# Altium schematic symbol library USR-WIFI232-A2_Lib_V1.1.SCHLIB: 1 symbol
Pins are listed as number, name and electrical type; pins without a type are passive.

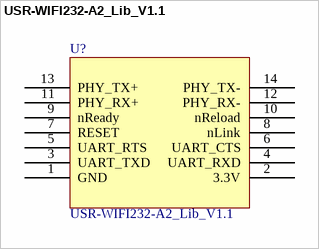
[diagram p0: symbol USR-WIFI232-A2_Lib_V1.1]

## USR-WIFI232-A2_Lib_V1.1
designator U?
footprint HA
pins: 1 GND, 2 3.3V, 3 UART_TXD, 4 UART_RXD, 5 UART_RTS, 6 UART_CTS, 7 RESET, 8 nLink, 9 nReady, 10 nReload, 11 PHY_RX+, 12 PHY_RX-, 13 PHY_TX+, 14 PHY_TX-
2 alternate drawings of the same symbol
